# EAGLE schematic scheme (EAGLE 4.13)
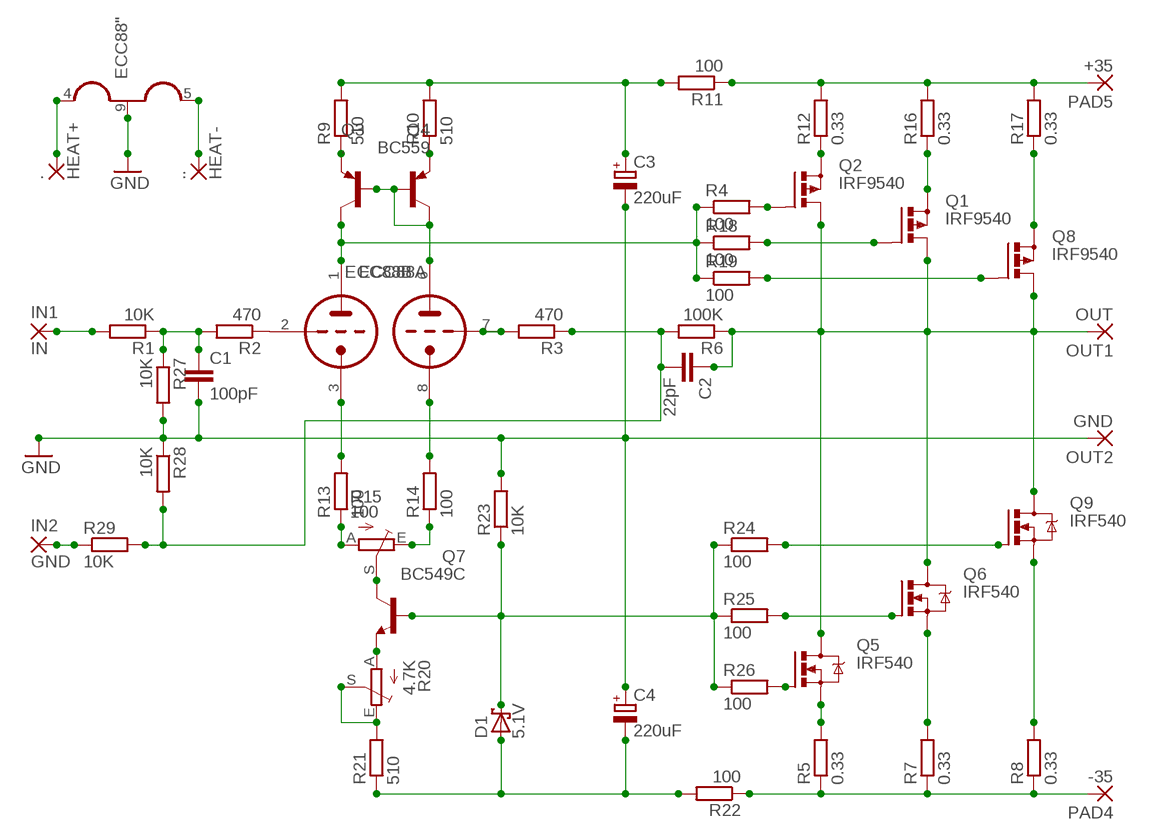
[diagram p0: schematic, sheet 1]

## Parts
.  HEAT+  3,81/1,4  [3,81/1,4]
..  HEAT-  3,81/1,4  [3,81/1,4]
C1  100pF  C-EU025-025X050  [C025-025X050]
C2  22pF  C-EU025-025X050  [C025-025X050]
C3  220uF  CPOL-EUE5-13  [E5-13]
C4  220uF  CPOL-EUE5-13  [E5-13]
D1  5.1V  BAT19  [DO35-10]
ECC88  ECC88-P  [NOVAL]
IN1  IN  3,81/1,4  [3,81/1,4]
IN2  GND  3,81/1,4  [3,81/1,4]
OUT1  OUT  3,81/1,4  [3,81/1,4]
OUT2  GND  3,81/1,4  [3,81/1,4]
PAD4  -35  3,81/1,4  [3,81/1,4]
PAD5  +35  3,81/1,4  [3,81/1,4]
Q1  IRF9540  IRF9530  [TO220BV]
Q2  IRF9540  IRF9530  [TO220BV]
Q3  .  BC559C  [TO92-EBC]
Q4  BC559  BC559C  [TO92-EBC]
Q5  IRF540  [TO220BV]
Q6  IRF540  [TO220BV]
Q7  BC549C  [TO92-EBC]
Q8  IRF9540  IRF9530  [TO220BV]
Q9  IRF540  [TO220BV]
R1  10K  R-EU_0207/10  [0207/10]
R2  470  R-EU_0207/10  [0207/10]
R3  470  R-EU_0207/10  [0207/10]
R4  100  R-EU_0207/10  [0207/10]
R5  0.33  R-EU_0922/22  [0922/22]
R6  100K  R-EU_0207/10  [0207/10]
R7  0.33  R-EU_0922/22  [0922/22]
R8  0.33  R-EU_0922/22  [0922/22]
R9  510  R-EU_0207/10  [0207/10]
R10  510  R-EU_0207/10  [0207/10]
R11  100  R-EU_0207/10  [0207/10]
R12  0.33  R-EU_0922/22  [0922/22]
R13  100  R-EU_0207/10  [0207/10]
R14  100  R-EU_0207/10  [0207/10]
R15  100  TRIM_EU-CA6H  [CA6H]
R16  0.33  R-EU_0922/22  [0922/22]
R17  0.33  R-EU_0922/22  [0922/22]
R18  100  R-EU_0207/10  [0207/10]
R19  100  R-EU_0207/10  [0207/10]
R20  4.7K  TRIM_EU-CA6H  [CA6H]
R21  510  R-EU_0207/10  [0207/10]
R22  100  R-EU_0207/10  [0207/10]
R23  10K  R-EU_0207/10  [0207/10]
R24  100  R-EU_0207/10  [0207/10]
R25  100  R-EU_0207/10  [0207/10]
R26  100  R-EU_0207/10  [0207/10]
R27  10K  R-EU_0207/10  [0207/10]
R28  10K  R-EU_0207/10  [0207/10]
R29  10K  R-EU_0207/10  [0207/10]

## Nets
GND: C1.2 C3.- C4.+ ECC88.9(":H2) OUT2.1(P) R23.2 R27.2 R28.1
N$1: IN1.1(P) R1.2
N$2: ECC88.2(A:TG) R2.1
N$3: ECC88.7(B:TG) R3.2
N$4: ECC88.6(B:TA) Q3.B Q3.C Q4.B
N$5: ECC88.1(A:TA) Q4.C R4.1 R18.1 R19.1
N$6: Q6.S R7.2
N$7: Q1.S R16.1
N$8: C2.2 R3.1 R6.2 R28.2 R29.2
N$9: C2.1 OUT1.1(P) Q1.D Q2.D Q5.D Q6.D Q8.D Q9.D R6.1
N$10: Q2.S R12.1
N$11: Q1.G R18.2
N$12: Q4.E R9.1
N$13: Q3.E R10.1
N$14: C3.+ R9.2 R10.2 R11.2
N$15: PAD5.1(P) R11.1 R12.2 R16.2 R17.2
N$16: Q2.G R4.2
N$17: ECC88.3(A:TK) R13.2
N$18: ECC88.8(B:TK) R14.2
N$19: R13.1 R15.A
N$20: R14.1 R15.E
N$21: Q7.C R15.S
N$22: Q5.G R26.2
N$23: Q5.S R5.2
N$24: ..1(P) ECC88.4(":H1)
N$25: Q9.G R24.2
N$26: D1.C Q7.B R23.1 R24.1 R25.1 R26.1
N$27: Q7.E R20.A
N$28: R20.E R20.S R21.2
N$29: PAD4.1(P) R5.1 R7.1 R8.1 R22.1
N$30: Q8.G R19.2
N$31: C4.- D1.A R21.1 R22.2
N$32: Q8.S R17.1
N$33: Q6.G R25.2
N$34: Q9.S R8.2
N$35: C1.1 R1.1 R2.2 R27.1
N$36: IN2.1(P) R29.1
N$37: ...1(P) ECC88.5(":H3)

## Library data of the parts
. .. IN1 IN2 OUT1 OUT2 PAD4 PAD5 = wirepad:3,81/1,4: THROUGH-HOLE PAD
C1 C2 = rcl:C-EU: CAPACITOR, European symbol
C3 C4 = rcl:CPOL-EU: POLARIZED CAPACITOR, European symbol
D1 = diode:BAT19: DIODE
ECC88 = tubes:ECC88-P
Q1 Q2 Q8 = transistor-power:IRF9530: N-CHANNEL MOS FET
Q3 Q4 = transistor-pnp:BC559*: PNP Transistror
Q5 Q6 Q9 = transistor-power:IRF540: HEXFET Power MOSFET
Q7 = transistor-npn:BC549*: NPN Transistor
R1-R14 R16-R19 R21-R29 = rcl:R-EU_: RESISTOR, European symbol
R15 R20 = pot:TRIM_EU-: POTENTIOMETER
